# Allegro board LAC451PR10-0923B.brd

Outline 305.5 x 142.45 mm; copper layers: TOP, GND1, IN1, GND2, IN2, IN3, VCC, IN4, GND3, BOTTOM. Coordinates in mm from the lower left corner of the outline.

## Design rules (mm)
constraint set DEFAULT: min track width 0.102, pair gap 0.127
net group CLK_ITPXDP_N: nets CLK_ITPXDP_N CLK_ITPXDP_P
net group CPU_DP3_AUXN: nets CPU_DP3_AUXN CPU_DP3_AUXP
net group CRT_12_20: nets HUB_VGA_HSYNC HUB_VGA_VSYNC
net group CSS_1: nets CSSN_1 CSSP_1
net group DCIN_JACK: nets +DCIN_JACK -DCIN_JACK
net group DDR-ALERT: nets DDR_A_ALERT# DDR_B_ALERT#
net group DIFFPAIR0: nets SD/MMCDAT0/RCLK+_R SD/MMCDAT1/RCLK-_R
net group DIFFPAIR1: nets CLK_ITPXDP_N_R CLK_ITPXDP_P_R
net group GT1N: nets GT1N GT1P
net group ISUMN_GT: nets ISUMN_GT ISUMP_GT
net group ISUMN_IA: nets ISUMN_IA ISUMP_IA
net group PECI-S: nets PECI_EC PECI_EC_R
net group VSA_SEN-: nets VSA_SEN+ VSA_SEN-
net group ASYN-COMP: nets CFG_RCOMP CPU_POPIRCOMP EDP_COMP EDRAM_OPIO_RCOMP EMMC_RCOMP EOPIO_RCOMP PCH_POPIRCOMP PCIE_RCOMPN PCIE_RCOMPP SD_RCOMP SM_RCOMP0 SM_RCOMP1 SM_RCOMP2 USBCOMP
net group ASYN_12: nets H_CATERR# H_CPUPWRGD H_CPUPWRGD_R H_PROCHOT# H_PROCHOT#_R H_PROCHOT#_R1 H_THERMTRIP# H_VCCST_PWRGD H_VCCST_PWRGD_XDP PCH_PLTRST# PCH_PLTRST#_EC PLTRST_5048# PLTRST_LAN# PLTRST_TPM# PLTRST_VMM2320# THERMATRIP2# THERMATRIP3# VCCST_PWRGD XDP_OBS0 XDP_OBS0_R XDP_OBS1 XDP_OBS1_R XDP_OBS2_R XDP_OBS3_R
net group ASYN_20: nets +DDR_VREF_A_DQ +DDR_VREF_B_DQ +DDR_VREF_CA DDR_DRAMRST# DDR_DRAMRST#_R
net group BC BUS_12/15: nets BC_CLK_ECE1117 BC_CLK_ECE5048 BC_DAT_ECE1117 BC_DAT_ECE5048
net group CARD-S_12: nets SD/MMCCD# SD/MMCCLK SD/MMCCLK_R SD/MMCCMD SD/MMCCMD_R SD/MMCDAT2 SD/MMCDAT2_R SD/MMCDAT3 SD/MMCDAT3_R SDWP
net group CARD_20: nets SD/MMCDAT0/RCLK+ SD/MMCDAT1/RCLK- SD_UHS2_D0N SD_UHS2_D0P SD_UHS2_D1N SD_UHS2_D1P
net group CLINK-S_10: nets PCH_CL_CLK1 PCH_CL_DATA1 PCH_CL_RST1#
net group CLK-S_15: nets CLK_PCI_DOCK CLK_PCI_LPDEBUG CLK_PCI_MEC CLKREQ_PCIE#0 CLKREQ_PCIE#1 CLKREQ_PCIE#2 CLKREQ_PCIE#3 CLKREQ_PCIE#4 CLKREQ_PCIE#5 CPU_XDP_TCLK DAI_12MHZ# DAI_BCLK# DMIC_CLK0 DMIC_CLK_CODEC HDA_BIT_CLK HDA_BIT_CLK_R HUB_SPI_CLK I2S_BCLK I2S_MCLK JTAG_CLK MSCLK PCH_JTAG_TCK PCH_RTCRST# PCI_CLK_LPC0 PCI_CLK_LPC1 SRTCRST# SUSCLK SUSCLK_R WIGIG_32KHZ XCLK_BIASREF
net group CLK-S_20: nets CLK_27M_IN CLK_27M_OUT CLK_27M_OUT_R MEC_XTAL1 MEC_XTAL2 MEC_XTAL2_R PCH_RTCX1 PCH_RTCX2 PCH_RTCX2_R XTAL24_IN XTAL24_OUT XTAL24_OUT_R XTALI XTALO XTALO_R
net group CODEC-HP_10: nets AUD_HP_OUT_L AUD_HP_OUT_L1 AUD_HP_OUT_R AUD_HP_OUT_R1 AUD_OUT_L AUD_OUT_R
net group CODEC-SENSE_10: nets AUD_HP_NB_SENSE AUD_SENSE_A AUD_SENSE_B
net group CODEC_10: nets RING2 RING2_R SLEEVE SLEEVE_R
net group CRITICAL S_15: nets INTRUDER# PCH_DPWROK PCH_PCIE_WAKE# PCH_PWROK PCH_RSMRST# PCH_RSMRST#_Q PCIE_WAKE# PCIE_WAKE#_R RESET_OUT# RESET_OUT#_R SIO_PWRBTN# SIO_RCIN#
net group CRT_20_30: nets HUB_VGA_BLUE HUB_VGA_GREEN HUB_VGA_RED
net group DDRA-CKE: nets DDR_A_CKE0 DDR_A_CKE1 DDR_A_CKE2 DDR_A_CKE3
net group DDRA-CLK: nets DDR_A_CLK0 DDR_A_CLK1 DDR_A_CLK#0 DDR_A_CLK#1
net group DDRA-CMD: nets DDR_A_ACT# DDR_A_BA0 DDR_A_BA1 DDR_A_BG0 DDR_A_BG1 DDR_A_MA0 DDR_A_MA1 DDR_A_MA2 DDR_A_MA3 DDR_A_MA4 DDR_A_MA5 DDR_A_MA6 DDR_A_MA7 DDR_A_MA8 DDR_A_MA9 DDR_A_MA10 DDR_A_MA11 DDR_A_MA12 DDR_A_MA13 DDR_A_MA14 DDR_A_MA15 DDR_A_MA16 DDR_A_PARITY
net group DDRA-CTL: nets DDR_A_CS#0 DDR_A_CS#1 DDR_A_ODT0 DDR_A_ODT1
net group DDRA-D0: nets DDR_A_D0 DDR_A_D1 DDR_A_D2 DDR_A_D3 DDR_A_D4 DDR_A_D5 DDR_A_D6 DDR_A_D7
net group DDRA-D1: nets DDR_A_D8 DDR_A_D9 DDR_A_D10 DDR_A_D11 DDR_A_D12 DDR_A_D13 DDR_A_D14 DDR_A_D15
net group DDRA-D2: nets DDR_A_D16 DDR_A_D17 DDR_A_D18 DDR_A_D19 DDR_A_D20 DDR_A_D21 DDR_A_D22 DDR_A_D23
net group DDRA-D3: nets DDR_A_D24 DDR_A_D25 DDR_A_D26 DDR_A_D27 DDR_A_D28 DDR_A_D29 DDR_A_D30 DDR_A_D31
net group DDRA-D4: nets DDR_A_D32 DDR_A_D33 DDR_A_D34 DDR_A_D35 DDR_A_D36 DDR_A_D37 DDR_A_D38 DDR_A_D39
net group DDRA-D5: nets DDR_A_D40 DDR_A_D41 DDR_A_D42 DDR_A_D43 DDR_A_D44 DDR_A_D45 DDR_A_D46 DDR_A_D47
net group DDRA-D6: nets DDR_A_D48 DDR_A_D49 DDR_A_D50 DDR_A_D51 DDR_A_D52 DDR_A_D53 DDR_A_D54 DDR_A_D55
net group DDRA-D7: nets DDR_A_D56 DDR_A_D57 DDR_A_D58 DDR_A_D59 DDR_A_D60 DDR_A_D61 DDR_A_D62 DDR_A_D63
net group DDRA-DQS: nets DDR_A_DQS0 DDR_A_DQS1 DDR_A_DQS2 DDR_A_DQS3 DDR_A_DQS4 DDR_A_DQS5 DDR_A_DQS6 DDR_A_DQS7 DDR_A_DQS#0 DDR_A_DQS#1 DDR_A_DQS#2 DDR_A_DQS#3 DDR_A_DQS#4 DDR_A_DQS#5 DDR_A_DQS#6 DDR_A_DQS#7
net group DDRB-CKE: nets DDR_B_CKE0 DDR_B_CKE1 DDR_B_CKE2 DDR_B_CKE3
net group DDRB-CLK: nets DDR_B_CLK0 DDR_B_CLK1 DDR_B_CLK#0 DDR_B_CLK#1
net group DDRB-CMD: nets DDR_B_ACT# DDR_B_BA0 DDR_B_BA1 DDR_B_BG0 DDR_B_BG1 DDR_B_MA0 DDR_B_MA1 DDR_B_MA2 DDR_B_MA3 DDR_B_MA4 DDR_B_MA5 DDR_B_MA6 DDR_B_MA7 DDR_B_MA8 DDR_B_MA9 DDR_B_MA10 DDR_B_MA11 DDR_B_MA12 DDR_B_MA13 DDR_B_MA14 DDR_B_MA15 DDR_B_MA16 DDR_B_PARITY
net group DDRB-CTL: nets DDR_B_CS#0 DDR_B_CS#1 DDR_B_ODT0 DDR_B_ODT1
net group DDRB-D0: nets DDR_B_D0 DDR_B_D1 DDR_B_D2 DDR_B_D3 DDR_B_D4 DDR_B_D5 DDR_B_D6 DDR_B_D7
net group DDRB-D1: nets DDR_B_D8 DDR_B_D9 DDR_B_D10 DDR_B_D11 DDR_B_D12 DDR_B_D13 DDR_B_D14 DDR_B_D15
net group DDRB-D2: nets DDR_B_D16 DDR_B_D17 DDR_B_D18 DDR_B_D19 DDR_B_D20 DDR_B_D21 DDR_B_D22 DDR_B_D23
net group DDRB-D3: nets DDR_B_D24 DDR_B_D25 DDR_B_D26 DDR_B_D27 DDR_B_D28 DDR_B_D29 DDR_B_D30 DDR_B_D31
net group DDRB-D4: nets DDR_B_D32 DDR_B_D33 DDR_B_D34 DDR_B_D35 DDR_B_D36 DDR_B_D37 DDR_B_D38 DDR_B_D39
net group DDRB-D5: nets DDR_B_D40 DDR_B_D41 DDR_B_D42 DDR_B_D43 DDR_B_D44 DDR_B_D45 DDR_B_D46 DDR_B_D47
net group DDRB-D6: nets DDR_B_D48 DDR_B_D49 DDR_B_D50 DDR_B_D51 DDR_B_D52 DDR_B_D53 DDR_B_D54 DDR_B_D55
net group DDRB-D7: nets DDR_B_D56 DDR_B_D57 DDR_B_D58 DDR_B_D59 DDR_B_D60 DDR_B_D61 DDR_B_D62 DDR_B_D63
net group DDRB-DQS: nets DDR_B_DQS0 DDR_B_DQS1 DDR_B_DQS2 DDR_B_DQS3 DDR_B_DQS4 DDR_B_DQS5 DDR_B_DQS6 DDR_B_DQS7 DDR_B_DQS#0 DDR_B_DQS#1 DDR_B_DQS#2 DDR_B_DQS#3 DDR_B_DQS#4 DDR_B_DQS#5 DDR_B_DQS#6 DDR_B_DQS#7
net group DP-DDI2_12_15: nets CPU_DP2_AUXN CPU_DP2_AUXN_C CPU_DP2_AUXP CPU_DP2_AUXP_C CPU_DP2_N0 CPU_DP2_N0_C CPU_DP2_N1 CPU_DP2_N1_C CPU_DP2_N2 CPU_DP2_N2_C CPU_DP2_N3 CPU_DP2_N3_C CPU_DP2_P0 CPU_DP2_P0_C CPU_DP2_P1 CPU_DP2_P1_C CPU_DP2_P2 CPU_DP2_P2_C CPU_DP2_P3 CPU_DP2_P3_C
net group DP-HUB_12_15: nets HUB_DP0_AUXN HUB_DP0_AUXN_C HUB_DP0_AUXP HUB_DP0_AUXP_C HUB_DP0_N0 HUB_DP0_N0_C HUB_DP0_N0_R HUB_DP0_N1 HUB_DP0_N1_C HUB_DP0_N1_R HUB_DP0_N2 HUB_DP0_N2_C HUB_DP0_N2_R HUB_DP0_N3 HUB_DP0_N3_C HUB_DP0_N3_R HUB_DP0_P0 HUB_DP0_P0_C HUB_DP0_P0_R HUB_DP0_P1 HUB_DP0_P1_C HUB_DP0_P1_R HUB_DP0_P2 HUB_DP0_P2_C HUB_DP0_P2_R HUB_DP0_P3 HUB_DP0_P3_C HUB_DP0_P3_R HUB_DP1_AUXN HUB_DP1_AUXN_C HUB_DP1_AUXP HUB_DP1_AUXP_C HUB_DP1_N0 HUB_DP1_N0_C HUB_DP1_N0_R HUB_DP1_N1 HUB_DP1_N1_C HUB_DP1_N1_R HUB_DP1_N2 HUB_DP1_N2_C HUB_DP1_N2_R HUB_DP1_N3 HUB_DP1_N3_C HUB_DP1_N3_R HUB_DP1_P0 HUB_DP1_P0_C HUB_DP1_P0_R HUB_DP1_P1 HUB_DP1_P1_C HUB_DP1_P1_R HUB_DP1_P2 HUB_DP1_P2_C HUB_DP1_P2_R HUB_DP1_P3 HUB_DP1_P3_C HUB_DP1_P3_R HUB_SW1_AUXN HUB_SW1_AUXP HUB_SW2_AUXN HUB_SW2_AUXP
net group DP-SW1_12_15: nets SW1_DP1_AUXN SW1_DP1_AUXP SW1_DP1_N0 SW1_DP1_N0_C SW1_DP1_N1 SW1_DP1_N1_C SW1_DP1_N2 SW1_DP1_N2_C SW1_DP1_N3 SW1_DP1_N3_C SW1_DP1_P0 SW1_DP1_P0_C SW1_DP1_P1 SW1_DP1_P1_C SW1_DP1_P2 SW1_DP1_P2_C SW1_DP1_P3 SW1_DP1_P3_C SW1_DP2_AUXN SW1_DP2_AUXP SW1_DP2_N0 SW1_DP2_N0_C SW1_DP2_N1 SW1_DP2_N1_C SW1_DP2_N2 SW1_DP2_N2_C SW1_DP2_N3 SW1_DP2_N3_C SW1_DP2_P0 SW1_DP2_P0_C SW1_DP2_P1 SW1_DP2_P1_C SW1_DP2_P2 SW1_DP2_P2_C SW1_DP2_P3 SW1_DP2_P3_C
net group DP-SW2_12_15: nets SW2_DP1_AUXN SW2_DP1_AUXN_C SW2_DP1_AUXP SW2_DP1_AUXP_C SW2_DP1_N0 SW2_DP1_N0_C SW2_DP1_N1 SW2_DP1_N1_C SW2_DP1_N2 SW2_DP1_N2_C SW2_DP1_N3 SW2_DP1_N3_C SW2_DP1_P0 SW2_DP1_P0_C SW2_DP1_P1 SW2_DP1_P1_C SW2_DP1_P2 SW2_DP1_P2_C SW2_DP1_P3 SW2_DP1_P3_C SW2_DP2_AUXN SW2_DP2_AUXN_C SW2_DP2_AUXP SW2_DP2_AUXP_C SW2_DP2_N0 SW2_DP2_N0_C SW2_DP2_N1 SW2_DP2_N1_C SW2_DP2_N2 SW2_DP2_N2_C SW2_DP2_N3 SW2_DP2_N3_C SW2_DP2_P0 SW2_DP2_P0_C SW2_DP2_P1 SW2_DP2_P1_C SW2_DP2_P2 SW2_DP2_P2_C SW2_DP2_P3 SW2_DP2_P3_C
net group EDP_12_15: nets EDP_AUXN EDP_AUXN_C EDP_AUXP EDP_AUXP_C EDP_TXN0 EDP_TXN0_C EDP_TXN1 EDP_TXN1_C EDP_TXP0 EDP_TXP0_C EDP_TXP1 EDP_TXP1_C
net group EMI: nets BIA_PWM BIA_PWM_EC BST_3V BST_5V CLKRUN# DAI_LRCK# DMIC0 EC5048_TX EDP_BIA_PWM HOST_DEBUG_TX SD_GPIO TP_LAN_JTAG_TCK
net group ESD-GND: nets CPU_XDP_PRDY# CPU_XDP_PREQ# CPU_XDP_TDI CPU_XDP_TDO CPU_XDP_TMS CPU_XDP_TRST# PCH_JTAG_TDI PCH_JTAG_TDO PCH_JTAG_TMS POWER_SW#_MB POWER_SW_IN# RUNPWROK
net group ESD-NOCROSS-MOAT: nets CFG0 CFG1 CFG2 CFG3 CFG4 CFG5 CFG6 CFG7 CFG8 CFG9 CFG10 CFG11 CFG12 CFG13 CFG14 CFG15 CFG16 CFG17 CFG18 CFG19 SIO_EXT_SMI#
net group HDA_5_15: nets HDA_RST# HDA_RST#_R HDA_SDIN0 HDA_SDIN0_R HDA_SDOUT HDA_SDOUT_R HDA_SYNC HDA_SYNC_R
net group HDMI_12_15: nets CPU_DP1_AUXN CPU_DP1_AUXP CPU_DP1_N0 CPU_DP1_N1 CPU_DP1_N2 CPU_DP1_N3 CPU_DP1_P0 CPU_DP1_P1 CPU_DP1_P2 CPU_DP1_P3 HDMI_CLKN HDMI_CLKP HDMI_L_CLKN HDMI_L_CLKP HDMI_L_TX_N0 HDMI_L_TX_N1 HDMI_L_TX_N2 HDMI_L_TX_P0 HDMI_L_TX_P1 HDMI_L_TX_P2 HDMI_TX_N0 HDMI_TX_N1 HDMI_TX_N2 HDMI_TX_P0 HDMI_TX_P1 HDMI_TX_P2
net group I2C_15: nets I2C_HUB_SCL I2C_HUB_SDA ISH_I2C2_SCL ISH_I2C2_SCL_R ISH_I2C2_SDA ISH_I2C2_SDA_R
net group MDI_20: nets LAN_MDIN0 LAN_MDIN0_L LAN_MDIN1 LAN_MDIN1_L LAN_MDIN2 LAN_MDIN2_L LAN_MDIN3 LAN_MDIN3_L LAN_MDIP0 LAN_MDIP0_L LAN_MDIP1 LAN_MDIP1_L LAN_MDIP2 LAN_MDIP2_L LAN_MDIP3 LAN_MDIP3_L SW_LAN0_MDIN0 SW_LAN0_MDIN1 SW_LAN0_MDIN2 SW_LAN0_MDIN3 SW_LAN0_MDIP0 SW_LAN0_MDIP1 SW_LAN0_MDIP2 SW_LAN0_MDIP3 SW_LAN1_MDIN0 SW_LAN1_MDIN1 SW_LAN1_MDIN2 SW_LAN1_MDIN3 SW_LAN1_MDIP0 SW_LAN1_MDIP1 SW_LAN1_MDIP2 SW_LAN1_MDIP3
net group PCIE_12: nets PCIE_PRX_C_DTX_N9 PCIE_PRX_C_DTX_N10 PCIE_PRX_C_DTX_N11 PCIE_PRX_C_DTX_N12 PCIE_PRX_C_DTX_P9 PCIE_PRX_C_DTX_P10 PCIE_PRX_C_DTX_P11 PCIE_PRX_C_DTX_P12 PCIE_PRX_C_RD_DTX_N11 PCIE_PRX_C_RD_DTX_N12 PCIE_PRX_C_RD_DTX_P11 PCIE_PRX_C_RD_DTX_P12 PCIE_PRX_DTX_N3 PCIE_PRX_DTX_N5 PCIE_PRX_DTX_N6 PCIE_PRX_DTX_N9 PCIE_PRX_DTX_N10 PCIE_PRX_DTX_N11 PCIE_PRX_DTX_N12 PCIE_PRX_DTX_P3 PCIE_PRX_DTX_P5 PCIE_PRX_DTX_P6 PCIE_PRX_DTX_P9 PCIE_PRX_DTX_P10 PCIE_PRX_DTX_P11 PCIE_PRX_DTX_P12 PCIE_PRX_RD_DTX_N11 PCIE_PRX_RD_DTX_N12 PCIE_PRX_RD_DTX_P11 PCIE_PRX_RD_DTX_P12 PCIE_PTX_C_DRX_N3 PCIE_PTX_C_DRX_N5 PCIE_PTX_C_DRX_N6 PCIE_PTX_C_DRX_N9 PCIE_PTX_C_DRX_N10 PCIE_PTX_C_DRX_N11 PCIE_PTX_C_DRX_N12 PCIE_PTX_C_DRX_P3 PCIE_PTX_C_DRX_P5 PCIE_PTX_C_DRX_P6 PCIE_PTX_C_DRX_P9 PCIE_PTX_C_DRX_P10 PCIE_PTX_C_DRX_P11 PCIE_PTX_C_DRX_P12 PCIE_PTX_C_RD_DRX_N11 PCIE_PTX_C_RD_DRX_N12 PCIE_PTX_C_RD_DRX_P11 PCIE_PTX_C_RD_DRX_P12 PCIE_PTX_DRX_N3 PCIE_PTX_DRX_N5 PCIE_PTX_DRX_N6 PCIE_PTX_DRX_N9 PCIE_PTX_DRX_N10 PCIE_PTX_DRX_N11 PCIE_PTX_DRX_N12 PCIE_PTX_DRX_P3 PCIE_PTX_DRX_P5 PCIE_PTX_DRX_P6 PCIE_PTX_DRX_P9 PCIE_PTX_DRX_P10 PCIE_PTX_DRX_P11 PCIE_PTX_DRX_P12 PCIE_PTX_RD_DRX_N11 PCIE_PTX_RD_DRX_N12 PCIE_PTX_RD_DRX_P11 PCIE_PTX_RD_DRX_P12
net group PLAT-CLK_12: nets CLK_PCIE_N0 CLK_PCIE_N1 CLK_PCIE_N2 CLK_PCIE_N3 CLK_PCIE_N4 CLK_PCIE_N5 CLK_PCIE_P0 CLK_PCIE_P1 CLK_PCIE_P2 CLK_PCIE_P3 CLK_PCIE_P4 CLK_PCIE_P5
net group RJ45_20: nets RJ45_MDIN0 RJ45_MDIN1 RJ45_MDIN2 RJ45_MDIN3 RJ45_MDIP0 RJ45_MDIP1 RJ45_MDIP2 RJ45_MDIP3
net group SATA_12: nets SATA_PRX_C_DTX_N1 SATA_PRX_C_DTX_P1 SATA_PRX_DTX_N1 SATA_PRX_DTX_P1 SATA_PTX_C_DRX_N1 SATA_PTX_C_DRX_P1 SATA_PTX_DRX_N1 SATA_PTX_DRX_P1
net group SD-NOCROSS-MOAT: nets DOCK_POR_RST# JTAG_RST# ME_SUS_PWR_ACK SUSACK# USB_OC0# USB_OC1# USB_OC2#
net group SENSE_25: nets VCC_GT_SENSE VCCIO_SENSE VCCSENSE VSS_GT_SENSE VSSIO_SENSE VSSSENSE
net group SIM_15: nets UIM_CLK UIM_DATA UIM_RESET
net group SMB_15: nets CHARGER_SMBCLK CHARGER_SMBDAT CLK_KBD CLK_MSE CLK_TP_SIO CPU_DP1_CTRL_CLK CPU_DP1_CTRL_DATA CPU_DP2_CTRL_CLK CPU_DP2_CTRL_DATA DAT_KBD DAT_MSE DAT_TP_SIO DDR_XDP_WAN_SMBCLK DDR_XDP_WAN_SMBDAT DOCK_SMB_CLK DOCK_SMB_DAT GPU_SMBCLK GPU_SMBDAT HDMI_CTRL_CLK HDMI_CTRL_DATA HUB_DP0_SCL HUB_DP0_SDA HUB_DP1_SCL HUB_DP1_SDA HUB_VGA_SCL HUB_VGA_SDA MEM_SMBCLK MEM_SMBDATA PBAT_SMBCLK PBAT_SMBCLK_C PBAT_SMBDAT PBAT_SMBDAT_C SML0_SMBCLK SML0_SMBDATA SML1_SMBCLK SML1_SMBDATA USH_SMBCLK USH_SMBDAT
net group SPI-CLK_15: nets PCH_SPI_CLK PCH_SPI_CLK_0_R PCH_SPI_CLK_1_R PCH_SPI_CLK_2_R PCH_SPI_CLK_R1
net group SPI-S_5: nets HUB_SPI_CS# HUB_SPI_DIN HUB_SPI_DO HUB_SPI_HOLD HUB_SPI_WP# PCH_SPI_CS#0 PCH_SPI_CS#0_R1 PCH_SPI_CS#0_R2 PCH_SPI_CS#1 PCH_SPI_CS#1_R1 PCH_SPI_CS#1_R2 PCH_SPI_CS#2 PCH_SPI_CS#2_R PCH_SPI_D0 PCH_SPI_D0_0_R PCH_SPI_D0_1_R PCH_SPI_D0_2_R PCH_SPI_D0_R1 PCH_SPI_D1 PCH_SPI_D1_0_R PCH_SPI_D1_1_R PCH_SPI_D1_2_R PCH_SPI_D1_R1 PCH_SPI_D2 PCH_SPI_D2_0_R PCH_SPI_D2_1_R PCH_SPI_D2_R1 PCH_SPI_D3 PCH_SPI_D3_0_R PCH_SPI_D3_1_R PCH_SPI_D3_R1 PCH_SPI_DO2_XDP PCH_SPI_DO_XDP
net group SPK_20: nets INT_SPK_L+ INT_SPK_L- INT_SPK_R+ INT_SPK_R- INT_SPKR_L+ INT_SPKR_L- INT_SPKR_R+ INT_SPKR_R-
net group SVID_18: nets H_CPU_SVIDALRT# VIDALERT_N VIDSCLK VIDSOUT
net group THERMAL_20: nets DOCK_DCIN_IS+ DOCK_DCIN_IS- REM_DIODE1_N REM_DIODE1_P REM_DIODE2_N REM_DIODE2_P REM_DIODE4_N REM_DIODE4_P
net group USB20_12: nets SW_USB20_N1 SW_USB20_P1 USB20_N1 USB20_N1_R USB20_N2 USB20_N2_R USB20_N3 USB20_N3_R USB20_N4 USB20_N4_R USB20_N5 USB20_N6 USB20_N7 USB20_N8 USB20_N9 USB20_N9_R USB20_N10 USB20_P1 USB20_P1_R USB20_P2 USB20_P2_R USB20_P3 USB20_P3_R USB20_P4 USB20_P4_R USB20_P5 USB20_P6 USB20_P7 USB20_P8 USB20_P9 USB20_P9_R USB20_P10
net group USB30_12: nets USB3_PRX_DTX_N1 USB3_PRX_DTX_N2 USB3_PRX_DTX_N3 USB3_PRX_DTX_N4 USB3_PRX_DTX_N5 USB3_PRX_DTX_P1 USB3_PRX_DTX_P2 USB3_PRX_DTX_P3 USB3_PRX_DTX_P4 USB3_PRX_DTX_P5 USB3_PRX_L_DTX_N1 USB3_PRX_L_DTX_N3 USB3_PRX_L_DTX_N4 USB3_PRX_L_DTX_N5 USB3_PRX_L_DTX_P1 USB3_PRX_L_DTX_P3 USB3_PRX_L_DTX_P4 USB3_PRX_L_DTX_P5 USB3_PTX_C_DRX_N1 USB3_PTX_C_DRX_N3 USB3_PTX_C_DRX_N4 USB3_PTX_C_DRX_N5 USB3_PTX_C_DRX_P1 USB3_PTX_C_DRX_P3 USB3_PTX_C_DRX_P4 USB3_PTX_C_DRX_P5 USB3_PTX_DRX_N1 USB3_PTX_DRX_N2 USB3_PTX_DRX_N3 USB3_PTX_DRX_N4 USB3_PTX_DRX_N5 USB3_PTX_DRX_P1 USB3_PTX_DRX_P2 USB3_PTX_DRX_P3 USB3_PTX_DRX_P4 USB3_PTX_DRX_P5 USB3_PTX_L_DRX_N1 USB3_PTX_L_DRX_N3 USB3_PTX_L_DRX_N4 USB3_PTX_L_DRX_N5 USB3_PTX_L_DRX_P1 USB3_PTX_L_DRX_P3 USB3_PTX_L_DRX_P4 USB3_PTX_L_DRX_P5
net group W10: nets BAT1_LED# BAT2_LED# BATT_WHITE# BATT_YELLOW#
nets with their own width: min track width 0.254; nets +1.0VO_DSW +3.3V_SPI +3.3V_SPI_R +5V_ALWP N25124064 PWM1_GT PWM_IA PWM_VSA
nets with their own width: min track width 0.508; nets +0.9V_LAN +1.0V_AMPHYPLL +1.0V_APLL +1.0V_APLLEBB +1.0V_CLK1 +1.0V_CLK2 +1.0V_CLK3 +1.0V_CLK4 +1.0V_CLK5 +1.0V_CLK6 +1.0V_DTS +1.0V_MPHYAON +1.0V_PRIM +1.0V_PRIM_CORE +1.0V_PRIM_XDP +1.0V_VCCST +1.0V_VCCST_C +1.0V_VCCSTG +1.2V_LDO +1.5V_RUN +1.5V_RUN_AUDIO +1.8V_RUN_CARD +3.3V_ALW +3.3V_ALW2 +3.3V_ALW_DSW +3.3V_ALW_UE1 +3.3V_ALW_UE2 +3.3V_ALWP +3.3V_CAM +3.3V_M +3.3V_M_TPM +3.3V_M_UZ8 +3.3V_MMI_AUX +3.3V_RTC_LDO +3.3V_RUN +3.3V_RUN_AUDIO +3.3V_RUN_UZ3 +3.3V_TP +5V_ALW +5V_ALW2 +CAP_LDO +COINCELL +DC_IN +DC_IN_SS +DCIN +DDR_VREF_A_CA +DOCK_PWR_BAR +GND_CHASSIS +LOM_VCT +MIC1_VREF_OUT +NBDOCK_DC_IN_SS +PBATT +PECI_VREF +PWR_SRC +PWR_SRC_AC +RSVD_VCC3P3_1 +RTC_CELL +RTC_CELL_VBAT +SDC_IN +UZ12_TPM +VCC_CORE +VCC_CORE_G0 +VCC_CORE_G1 +VCC_GT +VCC_SA +VCC_SFR_OC +VCHGR +VDDA_AVDD1 +VDDA_PVDD +VR_CAP +VREFOUT +Z4012 ADJ GND GNDA N15438178 N36519054
nets with their own width: min track width 0.762; nets +1.0V_SRAM +3.3V_LAN_OUT
nets with their own width: min track width 1.016; nets +1.0V_RUN_VMM +1.0V_VMM_VDD +1.0V_VMM_VDDTX +1.0VS_VCCIO +1.8V_PGPPF +1.8V_PRIM +3.3V_1.8V_PGPPG +3.3V_ALW_PCH +3.3V_LAN +3.3V_LAN_UZ2 +3.3V_PGPPB +3.3V_PGPPC +3.3V_PGPPD +3.3V_PGPPE +3.3V_RUN_CARD +3.3V_RUN_VDDA +3.3V_RUN_VDDIO +3.3V_RUN_VMM +5V_RUN_AUDIO +5V_RUN_PVDD +V_DDR_REF
nets with their own width: min track width 1.27; nets +3.3V_MMI_IN
nets with their own width: min track width 1.524; nets +3.3V_1.8V_PGPPA +EDP_VDD +LCDVDD
nets with their own width: min track width 2.032; nets +1.0V_MPHYGT +3.3V_HDD +3.3V_WLAN +3.3V_WLAN_UZ3 +5V_RUN +BL_PWR_SRC +USB_LEFT_PWR +USB_REAR_PWR +VDISPLAY_VCC +VHDMI_VCC
nets with their own width: min track width 2.54; nets +3.3V_WWAN +5V_USB_CHG_PWR

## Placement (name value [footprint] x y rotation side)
C33  4.7U_0805_25V6-K  [C_0805]  174.09 126.6 270 bottom
C42  4.7P_0402_50V8C  [C_0402]  153.13 126.2 90 bottom
C43  4.7P_0402_50V8C  [C_0402]  155.84 126.2 90 bottom
C263  1U_0402_6.3V6K  [C_0402]  284.53 121.95 180 bottom
C294  0.1U_0402_25V6  [C_0402]  136.75 133.43 90 top
C295  0.1U_0402_25V6  [C_0402]  137.89 125.33 270 bottom
C296  0.1U_0402_25V6  [C_0402]  137.64 133.43 90 top
C297  0.1U_0402_25V6  [C_0402]  138.78 125.33 270 bottom
C298  0.1U_0402_25V6  [C_0402]  138.53 133.43 90 top
C299  0.1U_0402_25V6  [C_0402]  139.67 125.33 270 bottom
C300  0.1U_0402_25V6  [C_0402]  142.34 125.33 270 bottom
C301  0.1U_0402_25V6  [C_0402]  143.23 125.33 270 bottom
C302  0.1U_0402_25V6  [C_0402]  137.01 125.33 270 bottom
C303  0.1U_0402_25V6  [C_0402]  139.42 133.43 90 top
C304  0.1U_0402_25V6  [C_0402]  140.56 125.33 270 bottom
C305  0.1U_0402_25V6  [C_0402]  140.31 133.43 90 top
C306  0.1U_0402_25V6  [C_0402]  141.45 125.33 270 bottom
C307  0.1U_0402_25V6  [C_0402]  141.2 133.43 90 top
C308  0.1U_0402_25V6  [C_0402]  142.09 133.43 90 top
C309  0.1U_0402_25V6  [C_0402]  142.97 133.43 90 top
C310  0.033U_0402_16V7K  [C_0402]  145.01 127.11 270 bottom
C311  0.033U_0402_16V7K  [C_0402]  143.86 136.13 270 top
C312  0.01UF_0402_25V7K  [C_0402]  148.44 135.47 90 top
C313  0.01UF_0402_25V7K  [C_0402]  149.32 135.47 90 top
C314  0.01UF_0402_25V7K  [C_0402]  150.21 136.38 270 top
C315  0.01UF_0402_25V7K  [C_0402]  151.1 136.38 270 top
C316  1U_0402_6.3V6K  [C_0402]  176.43 124.82 180 bottom
C317  0.1U_0603_50V7K  [C_0603]  172.57 126.7 270 bottom
C318  0.1U_0603_50V7K  [C_0603]  135.04 132.37 0 top
C319  4.7P_0402_50V8C  [C_0402]  165.2 126.2 90 bottom
CA1  680P_0402_50V7K  [C_0402]  284.4 48.17 180 top
CA2  220P_0402_50V7K  [C_0402]  284.4 46.14 180 top
CA3  220P_0402_50V7K  [C_0402]  284.4 54.26 180 top
CA4  680P_0402_50V7K  [C_0402]  284.4 51.09 180 top
CA5  100P_0402_50V8J  [C_0402]  99.53 114.83 145 top
CA6  100P_0402_50V8J  [C_0402]  100.04 115.6 145 top
CA7  0.1U_0201_10V6K  [C_0201]  98.78 114.25 145 top
CA8  0.1U_0201_10V6K  [C_0201]  295.63 66.72 270 top
CA9  10U_0603_10V6M  [C_0603]  294.55 68.3 270 top
CA10  4.7U_0603_6.3V6K  [C_0603]  284.01 67.15 270 top
CA11  0.1U_0201_10V6K  [C_0201]  284.4 72.93 180 top
CA12  680P_0402_50V7K  [C_0402]  288.47 48.04 180 top
CA13  680P_0402_50V7K  [C_0402]  287.11 49.5 0 top
CA16  4.7U_0603_6.3V6K  [C_0603]  290.99 77.12 0 top
CA17  0.1U_0201_10V6K  [C_0201]  293.33 74.67 270 top
CA18  4.7U_0603_6.3V6K  [C_0603]  293.41 75.69 0 top
CA19  1000P_0402_50V7K  [C_0402]  280.13 32.24 270 top
CA22  1000P_0402_50V7K  [C_0402]  280.13 39.86 270 top
CA23  1000P_0402_50V7K  [C_0402]  280.13 33.1 90 top
CA24  1000P_0402_50V7K  [C_0402]  280.13 25.61 90 top
CA25  10U_0603_10V6M  [C_0603]  296.39 70.84 0 top
CA26  1U_0603_10V6K  [C_0603]  292.68 65.18 270 top
CA27  0.1U_0402_25V6  [C_0402]  285.18 63.95 90 top
CA28  0.1U_0402_25V6  [C_0402]  284.29 63.95 90 top
CA29  1U_0603_10V6K  [C_0603]  294.61 73 90 top
CA31  1U_0603_10V6K  [C_0603]  284.39 76.11 180 top
CA33  10P_0402_50V8J  [C_0402]  282.66 71.22 0 top
CA35  2.2U_0402_6.3V6M  [C_0402]  294.62 65.95 180 top
CA41  0.1U_0402_25V6  [C_0402]  281.45 61.12 0 top
CA43  4.7U_0603_6.3V6K  [C_0603]  290.01 64.41 270 top
CA44  4.7U_0603_6.3V6K  [C_0603]  291.21 64.41 270 top
CA45  0.1U_0201_10V6K  [C_0201]  286.7 76.74 180 top
CA46  10U_0603_10V6M  [C_0603]  287.94 77.89 0 top
CA47  0.1U_0201_10V6K  [C_0201]  288.06 76.74 0 top
CA48  10U_0603_10V6M  [C_0603]  286.93 77.89 180 top
CA49  1U_0603_10V6K  [C_0603]  297.78 72.04 180 top
CA50  0.1U_0201_10V6K  [C_0201]  284.14 68.1 180 top
CA51  4.7U_0603_6.3V6K  [C_0603]  294.42 60.87 0 top
CA52  4.7U_0603_6.3V6K  [C_0603]  291.05 75.92 0 top
CA53  4.7U_0603_6.3V6K  [C_0603]  281.53 70.07 90 top
CA54  22P_0402_50V8J  [C_0402]  281.79 73.94 90 top
CC3  27P_0402_50V8J  [C_0402]  177.7 70.17 90 top
CC4  27P_0402_50V8J  [C_0402]  176.81 70.17 90 top
CC5  27P_0402_50V8J  [C_0402]  180.05 70.11 90 top
CC6  27P_0402_50V8J  [C_0402]  179.16 70.11 90 top
CC7  33P_0402_50V8J  [C_0402]  187.11 89.55 180 bottom
CC8  33P_0402_50V8J  [C_0402]  185.39 100.03 90 bottom
CC9  0.1U_0201_10V6K  [C_0201]  187.17 100.03 90 bottom
CC10  0.1U_0201_10V6K  [C_0201]  186.88 93.86 270 bottom
CC21  15P_0402_50V8J  [C_0402]  153.59 111.11 180 bottom
CC22  15P_0402_50V8J  [C_0402]  154.45 111.11 0 bottom
CC23  15P_0402_50V8J  [C_0402]  179.49 89.45 270 top
CC24  1U_0402_6.3V6K  [C_0402]  168.64 73.34 270 top
CC25  1U_0402_6.3V6K  [C_0402]  203.81 78.19 90 bottom
CC26  12P_0402_50V8J  [C_0402]  181.32 89.44 0 top
CC27  22P_0402_50V8J  [C_0402]  165.38 69.59 90 top
CC28  0.1U_0201_10V6K  [C_0201]  129.59 125.08 0 top
CC29  0.1U_0201_10V6K  [C_0201]  129.55 124.01 0 top
CC30  0.1U_0201_10V6K  [C_0201]  145.59 117.7 180 bottom
CC32  0.1U_0402_25V6  [C_0402]  135.27 118.56 90 top
CC33  0.1U_0402_25V6  [C_0402]  127.61 128.77 270 top
CC174  10U_0402_6.3V6M  [C_0402]  144.74 72.59 180 top
CC175  10U_0402_6.3V6M  [C_0402]  150.92 74.98 0 top
CC176  10U_0402_6.3V6M  [C_0402]  159.05 74.43 270 top
CC177  10U_0402_6.3V6M  [C_0402]  146.55 74.52 270 top
CC178  10U_0402_6.3V6M  [C_0402]  151.89 71.95 270 top
CC179  10U_0402_6.3V6M  [C_0402]  155.5 72.11 270 top
CC181  1U_0402_6.3V6K  [C_0402]  148.55 88.36 180 top
CC182  1U_0402_6.3V6K  [C_0402]  155.65 86.55 90 top
CC185  1U_0402_6.3V6K  [C_0402]  149.37 89.25 0 top
CC186  1U_0402_6.3V6K  [C_0402]  149.37 88.36 0 top
CC194  1U_0402_6.3V6K  [C_0402]  152.89 87.56 180 top
CC195  1U_0402_6.3V6K  [C_0402]  164.41 106.08 90 bottom
CC199  1U_0402_6.3V6K  [C_0402]  159.22 112.73 0 top
CC202  1U_0402_6.3V6K  [C_0402]  161.19 98.67 180 top
CC203  1U_0402_6.3V6K  [C_0402]  164.96 98.2 270 top
CC204  1U_0402_6.3V6K  [C_0402]  173.87 88.16 0 top
CC205  1U_0402_6.3V6K  [C_0402]  163.01 90.39 270 top
CC206  1U_0402_6.3V6K  [C_0402]  162.39 92.46 90 top
CC207  1U_0402_6.3V6K  [C_0402]  165.25 91.58 180 top
CC208  1U_0402_6.3V6K  [C_0402]  165.05 93.3 0 top
CC209  1U_0402_6.3V6K  [C_0402]  163.27 92.47 0 top
CC210  47U_0805_6.3V6M  [C_0805]  176.86 114.14 0 top
CC211  1U_0402_6.3V6K  [C_0402]  164.98 94.95 0 top
CC212  1U_0402_6.3V6K  [C_0402]  174.83 91.21 270 top
CC213  1U_0402_6.3V6K  [C_0402]  162.1 87.28 180 top
CC214  0.1U_0201_10V6K  [C_0201]  177.76 77 90 bottom
CC215  1U_0402_6.3V6K  [C_0402]  161.6 89.49 90 top
CC216  1U_0402_6.3V6K  [C_0402]  169.85 111.29 180 top
CC217  1U_0402_6.3V6K  [C_0402]  162.13 91.42 180 top
CC218  1U_0402_6.3V6K  [C_0402]  163.04 95.01 180 top
CC219  47U_0805_6.3V6M  [C_0805]  170.03 110.44 90 bottom
CC220  47U_0805_6.3V6M  [C_0805]  163.42 111.45 90 top
CC221  47U_0805_6.3V6M  [C_0805]  168.25 110.44 90 bottom
CC222  1U_0402_6.3V6K  [C_0402]  168.22 93.25 180 top
CC223  0.1U_0201_10V6K  [C_0201]  173.02 88.01 90 top
CC224  1U_0402_6.3V6K  [C_0402]  172.26 87.57 90 top
CC225  47U_0805_6.3V6M  [C_0805]  191.1 96.18 90 top
CC226  47U_0805_6.3V6M  [C_0805]  162.6 110.44 90 bottom
CC248  10U_0402_6.3V6M  [C_0402]  148.55 87.47 180 top
CC249  10U_0402_6.3V6M  [C_0402]  149.37 87.47 0 top
CC250  1U_0402_6.3V6K  [C_0402]  157.38 88.78 90 top
CC251  1U_0402_6.3V6K  [C_0402]  148.55 89.25 180 top
CC252  1U_0402_6.3V6K  [C_0402]  157.44 87.45 180 top
CC253  1U_0402_6.3V6K  [C_0402]  156.49 88.78 90 top
CC254  1U_0402_6.3V6K  [C_0402]  147.95 74.52 270 top
CC255  1U_0402_6.3V6K  [C_0402]  150.8 74.05 270 top
CC256  1U_0402_6.3V6K  [C_0402]  156.85 73.3 270 top
CC257  1U_0402_6.3V6K  [C_0402]  153.78 74.18 270 top
CC264  1U_0402_6.3V6K  [C_0402]  171.36 110.32 90 bottom
CC265  1U_0402_6.3V6K  [C_0402]  166.01 89.9 180 top
CC266  0.01UF_0402_25V7K  [C_0402]  177.25 66.96 270 top
CC269  0.1U_0402_25V6  [C_0402]  110.16 122.34 180 bottom
CC270  0.1U_0201_10V6K  [C_0201]  169.44 71.48 180 top
CC271  47U_0805_6.3V6M  [C_0805]  178.5 64.4 270 top
CC272  47U_0805_6.3V6M  [C_0805]  276.92 3.46 180 top
CC273  47U_0805_6.3V6M  [C_0805]  166.15 119.58 90 bottom
CC274  47U_0805_6.3V6M  [C_0805]  191.09 91.77 90 top
CC279  22U_0603_6.3V6M  [C_0603]  180.82 69.07 0 top
CC280  22U_0603_6.3V6M  [C_0603]  180.82 67.86 0 top
CC281  0.1U_0201_10V6K  [C_0201]  173.52 111.74 270 bottom
CC282  22U_0603_6.3V6M  [C_0603]  146.02 88.74 270 top
CC283  22U_0603_6.3V6M  [C_0603]  165.2 117.13 180 top
CC284  22U_0603_6.3V6M  [C_0603]  165.2 115.86 180 top
CC285  22U_0603_6.3V6M  [C_0603]  165.07 118.84 180 top
CC286  22U_0603_6.3V6M  [C_0603]  160.82 72.81 270 top
CC287  22U_0603_6.3V6M  [C_0603]  141.15 118.28 90 top
CC288  1U_0402_6.3V6K  [C_0402]  160.68 89.51 90 top
CC294  22U_0603_6.3V6M  [C_0603]  139.16 74.27 270 top
CC295  22U_0603_6.3V6M  [C_0603]  149.46 71.98 270 top
CC296  22U_0603_6.3V6M  [C_0603]  158.85 72.34 270 top
CC297  10U_0402_6.3V6M  [C_0402]  151.13 87.18 90 top
CC300  100P_0402_50V8J  [C_0402]  125.12 99.6 0 bottom
CC301  100P_0402_50V8J  [C_0402]  133.41 110.47 180 bottom
CC302  0.1U_0402_25V6  [C_0402]  177.51 106.17 0 bottom
CC303  0.1U_0402_25V6  [C_0402]  141.72 107.88 90 bottom
CC304  0.1U_0402_25V6  [C_0402]  139.98 107.63 90 bottom
CC305  0.1U_0402_25V6  [C_0402]  138.36 110.42 180 bottom
CC306  0.1U_0402_25V6  [C_0402]  130.48 117.74 180 bottom
CC307  0.1U_0402_25V6  [C_0402]  110.16 124.48 180 bottom
CC308  0.1U_0402_25V6  [C_0402]  145.4 118.87 0 bottom
CC310  0.1U_0402_25V6  [C_0402]  128.19 108.86 180 bottom
CC311  15P_0402_50V8J  [C_0402]  163.54 72.75 180 top
CC312  0.1U_0402_25V6  [C_0402]  137.07 108.16 180 bottom
CC313  0.1U_0402_25V6  [C_0402]  190.55 85.58 0 top
CC314  0.1U_0402_25V6  [C_0402]  192.47 96.41 90 top
CD2  1U_0402_6.3V6K  [C_0402]  119.97 49.63 270 top
CD3  1U_0402_6.3V6K  [C_0402]  111.88 41.8 90 top
CD4  1U_0402_6.3V6K  [C_0402]  113.43 41.86 90 top
CD6  0.1U_0402_25V6  [C_0402]  107.74 44.83 90 top
CD7  1U_0402_6.3V6K  [C_0402]  118.42 41.5 90 top
CD8  1U_0402_6.3V6K  [C_0402]  110.37 41.68 90 top
CD9  1U_0402_6.3V6K  [C_0402]  118.46 49.6 270 top
CD10  1U_0402_6.3V6K  [C_0402]  115.08 49.68 270 top
CD11  1U_0402_6.3V6K  [C_0402]  111.85 49.63 270 top
CD12  10U_0603_10V6M  [C_0603]  121.83 41.32 90 top
CD13  10U_0603_10V6M  [C_0603]  109.19 41.22 90 top
CD14  10U_0603_10V6M  [C_0603]  110.32 50.15 270 top
CD15  10U_0603_10V6M  [C_0603]  116.75 50.15 270 top
CD16  10U_0603_10V6M  [C_0603]  123.49 41.31 90 top
CD17  10U_0603_10V6M  [C_0603]  115.05 41.35 90 top
CD18  10U_0603_10V6M  [C_0603]  113.43 50.14 270 top
CD19  10U_0603_10V6M  [C_0603]  121.63 50.15 270 top
CD20  330U_D3_2.5VY_R6M  [C_D3]  129.87 53.37 0 top
CD24  1U_0402_6.3V6K  [C_0402]  148.94 42.38 180 top
CD25  1U_0402_6.3V6K  [C_0402]  149.18 44.17 180 top
CD26  1U_0402_6.3V6K  [C_0402]  148.93 41.46 180 top
CD27  1U_0402_6.3V6K  [C_0402]  150.01 44.18 0 top
CD28  10U_0603_10V6M  [C_0603]  149.45 46.41 180 top
CD29  10U_0603_10V6M  [C_0603]  149.6 45.21 180 top
CD30  0.1U_0201_10V6K  [C_0201]  84.02 39.4 180 top
CD31  2.2U_0402_6.3V6M  [C_0402]  149.5 50.68 270 top
CD32  0.1U_0201_10V6K  [C_0201]  148.75 50.36 270 top
CD35  0.1U_0402_25V6  [C_0402]  190.84 41.04 180 top
CD36  0.022U_0402_16V7K  [C_0402]  129.69 41.25 90 top
CD37  1U_0402_6.3V6K  [C_0402]  192.68 41.35 90 top
CD38  1U_0402_6.3V6K  [C_0402]  195.5 41.4 90 top
CD39  1U_0402_6.3V6K  [C_0402]  198.98 41.18 90 top
CD40  1U_0402_6.3V6K  [C_0402]  205.33 49.89 270 top
CD41  1U_0402_6.3V6K  [C_0402]  201.78 49.89 270 top
CD42  1U_0402_6.3V6K  [C_0402]  194.03 50.02 270 top
CD43  1U_0402_6.3V6K  [C_0402]  191.23 50.02 270 top
CD44  1U_0402_6.3V6K  [C_0402]  205.32 41.58 90 top
CD45  10U_0603_10V6M  [C_0603]  192.57 50.08 270 top
CD46  10U_0603_10V6M  [C_0603]  189.66 50.08 270 top
CD47  10U_0603_10V6M  [C_0603]  200.25 50.52 270 top
CD48  10U_0603_10V6M  [C_0603]  203.55 50.52 270 top
CD49  10U_0603_10V6M  [C_0603]  203.46 41.26 90 top
CD50  10U_0603_10V6M  [C_0603]  200.28 41 90 top
CD51  10U_0603_10V6M  [C_0603]  197.34 41.11 90 top
CD52  10U_0603_10V6M  [C_0603]  194.02 41.17 90 top
CD53  330U_D3_2.5VY_R6M  [C_D3]  209.85 54.14 0 top
CD54  0.022U_0402_16V7K  [C_0402]  208.82 41.11 0 top
CD57  1U_0402_6.3V6K  [C_0402]  228.72 42.76 180 top
CD58  1U_0402_6.3V6K  [C_0402]  229.5 44.18 180 top
CD59  1U_0402_6.3V6K  [C_0402]  230.83 44.47 0 top
CD60  1U_0402_6.3V6K  [C_0402]  230.34 43.61 0 top
CD61  10U_0603_10V6M  [C_0603]  229.93 46.6 180 top
CD62  10U_0603_10V6M  [C_0603]  229.94 45.23 180 top
CD63  2.2U_0402_6.3V6M  [C_0402]  229.23 49.86 180 top
CD64  0.1U_0201_10V6K  [C_0201]  229.07 49.09 180 top
CD70  1U_0402_6.3V6K  [C_0402]  150.43 48.81 180 top
CD71  1U_0402_6.3V6K  [C_0402]  150.43 47.94 180 top
CD72  10U_0603_10V6M  [C_0603]  151.48 48.21 90 top
CD73  10U_0603_10V6M  [C_0603]  152.73 48.21 90 top
CD74  1U_0402_6.3V6K  [C_0402]  231.94 48.05 270 top
CD75  1U_0402_6.3V6K  [C_0402]  231.06 48.05 270 top
CD76  10U_0603_10V6M  [C_0603]  234.22 48.05 270 top
CD77  10U_0603_10V6M  [C_0603]  233 48.05 270 top
CD78  1U_0402_6.3V6K  [C_0402]  125.16 41.89 90 top
CD79  1U_0402_6.3V6K  [C_0402]  130.1 39.56 0 top
CD80  1U_0402_6.3V6K  [C_0402]  120.03 43.3 90 top
CD81  1U_0402_6.3V6K  [C_0402]  102.79 51.79 0 top
CD82  1U_0402_6.3V6K  [C_0402]  134.3 50.52 180 top
CD83  1U_0402_6.3V6K  [C_0402]  90.76 51.7 180 top
CD84  1U_0402_6.3V6K  [C_0402]  86.26 41.04 0 top
CD85  1U_0402_6.3V6K  [C_0402]  101.95 51.79 180 top
CD86  10U_0603_10V6M  [C_0603]  91.79 51.91 0 top
CD87  10U_0603_10V6M  [C_0603]  125.8 52.33 0 top
CD88  10U_0603_10V6M  [C_0603]  124.57 52.35 180 top
CD89  10U_0603_10V6M  [C_0603]  110.75 52.08 180 top
CD90  10U_0603_10V6M  [C_0603]  116.89 52.14 0 top
CD91  10U_0603_10V6M  [C_0603]  106.82 41.26 180 top
CD92  10U_0603_10V6M  [C_0603]  115.82 52.14 180 top
CD93  10U_0603_10V6M  [C_0603]  97.42 41.08 0 top
CD94  10U_0603_10V6M  [C_0603]  220.38 39.42 0 top
CD95  10U_0603_10V6M  [C_0603]  182.39 49.65 270 top
CD96  10U_0603_10V6M  [C_0603]  185.3 49.65 270 top
CD97  10U_0603_10V6M  [C_0603]  201.89 41.14 90 top
CD98  10U_0603_10V6M  [C_0603]  172.76 51.34 0 top
CD99  10U_0603_10V6M  [C_0603]  188.48 40.95 270 top
CD100  10U_0603_10V6M  [C_0603]  206.07 52.08 0 top
CD101  10U_0603_10V6M  [C_0603]  178.13 40.99 270 top
CD102  1U_0402_6.3V6K  [C_0402]  186.89 40.48 270 top
CD103  1U_0402_6.3V6K  [C_0402]  210.32 39.53 180 top
CD104  1U_0402_6.3V6K  [C_0402]  196.86 52.05 180 top
CD105  1U_0402_6.3V6K  [C_0402]  171.6 51.95 180 top
CD106  1U_0402_6.3V6K  [C_0402]  197.7 52.02 0 top
CD107  1U_0402_6.3V6K  [C_0402]  190.41 42.24 90 top
CD108  1U_0402_6.3V6K  [C_0402]  176.46 40.37 270 top
CD109  1U_0402_6.3V6K  [C_0402]  169.87 40.76 270 top
CE1  10U_0603_10V6M  [C_0603]  263.5 56.99 270 top
CE2  0.1U_0201_10V6K  [C_0201]  231.95 59.42 270 top
CE3  0.1U_0201_10V6K  [C_0201]  241.02 63.66 0 top
CE4  0.1U_0201_10V6K  [C_0201]  238.73 74.76 90 top
CE5  0.1U_0201_10V6K  [C_0201]  225.47 62.14 180 top
CE6  0.1U_0201_10V6K  [C_0201]  228.83 75.01 90 top
CE7  4.7U_0603_6.3V6K  [C_0603]  225.46 63.41 180 top
CE8  .047U_0402_16V7K  [C_0402]  228.39 59.42 270 top
CE9  33P_0402_50V8J  [C_0402]  230.6 75.93 270 top
CE10  1U_0402_6.3V6K  [C_0402]  245.08 79.36 270 top
CE11  0.1U_0201_10V6K  [C_0201]  252.53 74.61 90 top
CE12  1U_0402_6.3V6K  [C_0402]  243.3 78.44 90 top
CE13  0.1U_0201_10V6K  [C_0201]  252.96 59.29 270 top
CE14  1U_0402_6.3V6K  [C_0402]  253.85 59.29 270 top
CE15  1U_0402_6.3V6K  [C_0402]  255.75 75.01 90 top
CE16  0.1U_0201_10V6K  [C_0201]  246.3 65.95 180 top
CE17  0.1U_0201_10V6K  [C_0201]  246.56 71.79 180 top
CE18  0.1U_0201_10V6K  [C_0201]  260.58 59.29 270 top
CE19  0.1U_0201_10V6K  [C_0201]  258.8 75.01 90 top
CE20  0.1U_0201_10V6K  [C_0201]  254.73 74.63 90 top
CE21  10U_0603_10V6M  [C_0603]  264.74 56.99 270 top
CE22  0.1U_0201_10V6K  [C_0201]  256.51 59.42 270 top
CE23  0.1U_0201_10V6K  [C_0201]  262.53 67.73 0 top
CE24  2200P_0402_50V7K  [C_0402]  246.23 62.82 90 top
CE25  0.1U_0201_10V6K  [C_0201]  259.69 75.01 90 top
CE26  2200P_0402_50V7K  [C_0402]  246.23 60.92 90 top
CE27  2200P_0402_50V7K  [C_0402]  248.05 60.23 0 top
CE28  33P_0402_50V8J  [C_0402]  248.43 76.87 0 top
CE29  33P_0402_50V8J  [C_0402]  247.44 76.87 180 top
CE30  1U_0402_6.3V6K  [C_0402]  259.69 77.81 90 top
CE31  4.7U_0603_6.3V6K  [C_0603]  246.29 64.8 180 top
CE32  10U_0603_10V6M  [C_0603]  80.24 91.92 270 top
CE34  4.7P_0402_50V8C  [C_0402]  256.64 57.01 270 top
CE35  100P_0402_50V8J  [C_0402]  142.4 90.41 270 top
CE36  0.1U_0402_25V6  [C_0402]  258.3 59.29 0 top
CE37  100P_0402_50V8J  [C_0402]  225.14 53.3 90 top
CE38  0.1U_0402_25V6  [C_0402]  250.87 59.44 270 top
CE39  100P_0402_50V8J  [C_0402]  110.13 105.83 0 top
CE40  4700P_0402_25V7K  [C_0402]  246.3 66.84 180 top
CE44  1U_0402_6.3V6K  [C_0402]  243.25 76.81 180 top
CE45  1U_0402_6.3V6K  [C_0402]  245.1 75.92 90 top
CE46  100P_0402_50V8J  [C_0402]  270.3 66.58 180 bottom
CE47  4700P_0402_25V7K  [C_0402]  243.25 60.18 270 top
CE52  0.1U_0402_25V6  [C_0402]  251.44 54.92 180 top
CI1  100U_1206_6.3V6M  [C_1206]  57.7 131.22 90 bottom
CI3  0.1U_0201_10V6K  [C_0201]  72.18 125.71 270 top
CI4  0.1U_0402_25V6  [C_0402]  67.22 121.9 270 top
CI5  0.1U_0402_25V6  [C_0402]  66.33 121.9 270 top
CI6  10U_0603_10V6M  [C_0603]  79.54 125 0 top
CI7  0.1U_0201_10V6K  [C_0201]  79.88 126.15 0 top
CI8  100U_1206_6.3V6M  [C_1206]  79.74 127.88 90 bottom
CI10  0.1U_0201_10V6K  [C_0201]  93.55 125.97 270 top
CI11  10U_0603_10V6M  [C_0603]  100.49 124.62 0 top
CI12  0.1U_0201_10V6K  [C_0201]  100.78 125.74 0 top
CI13  0.1U_0402_25V6  [C_0402]  282.62 95.99 270 bottom
CI14  100U_1206_6.3V6M  [C_1206]  286.23 95.35 270 bottom
CI16  0.1U_0402_25V6  [C_0402]  283.51 95.99 270 bottom
CI17  0.1U_0201_10V6K  [C_0201]  284.33 93.79 270 bottom
CI19  0.1U_0201_10V6K  [C_0201]  273.62 103.32 180 top
CI27  0.1U_0402_25V6  [C_0402]  91.54 121.52 270 top
CI28  0.1U_0402_25V6  [C_0402]  92.43 121.52 270 top
CI29  0.1U_0402_25V6  [C_0402]  276.32 96.94 180 top
CI30  0.1U_0402_25V6  [C_0402]  276.32 97.82 180 top
CI31  10U_0402_6.3V6M  [C_0402]  273.78 104.17 180 top
CI32  150U_B2_6.3VM_R35M  [C_B2-NPM]  286.23 95.39 90 bottom
CI33  47U_0603_6.3V6M  [C_0603]  273.5 105.33 180 top
CI34  47U_0603_6.3V6M  [C_0603]  273.5 106.57 180 top
CL1  0.1U_0402_25V6  [C_0402]  257.02 88.76 270 top
CL2  0.1U_0402_25V6  [C_0402]  257.91 88.76 270 top
CL3  0.1U_0201_10V6K  [C_0201]  268.01 94.46 270 top
CL4  10U_0603_10V6M  [C_0603]  269.09 94.59 270 top
CL5  0.1U_0402_25V6  [C_0402]  259.69 87.84 90 top
CL6  0.1U_0402_25V6  [C_0402]  260.58 87.84 90 top
CL7  0.1U_0201_10V6K  [C_0201]  265.78 91.69 0 top
CL8  0.1U_0201_10V6K  [C_0201]  262.4 88.55 270 top
CL9  0.1U_0201_10V6K  [C_0201]  258.8 88.76 270 top
CL10  0.1U_0201_10V6K  [C_0201]  256.13 88.76 270 top
CL11  0.1U_0201_10V6K  [C_0201]  261.47 98.83 90 top
CL12  22U_0603_6.3V6M  [C_0603]  263.4 88.78 270 top
CL13  27P_0402_50V8J  [C_0402]  268.91 95.86 180 top
CL14  27P_0402_50V8J  [C_0402]  265.02 99.42 270 top
CL15  0.1U_0201_10V6K  [C_0201]  251.69 95.33 90 top
CL16  0.1U_0201_10V6K  [C_0201]  278.48 114.4 270 top
CL17  0.1U_0201_10V6K  [C_0201]  277.21 114.4 270 top
CL18  470P_0402_50V7K  [C_0402]  285.98 121.78 270 top
CL19  0.1U_0201_10V6K  [C_0201]  266.55 122.41 270 top
CL20  0.1U_0201_10V6K  [C_0201]  270.86 114.4 270 top
CL21  0.1U_0201_10V6K  [C_0201]  269.59 114.4 270 top
CL22  150P_1808_2.5KV8J  [C_1808]  290.18 128.81 180 bottom
CL25  0.1U_0201_10V6K  [C_0201]  255.5 109.56 90 top
CL26  0.1U_0201_10V6K  [C_0201]  255.5 106.38 90 top
CL27  0.1U_0201_10V6K  [C_0201]  267.43 109.56 90 top
CL28  22U_0805_6.3V6M  [C_0805]  254.7 93.89 180 top
CMOS1  SHORT PADS~D  [SHORTPADS-NPM]  204.95 78.65 90 bottom
CN19  0.1U_0201_10V6K  [C_0201]  30.57 57.82 0 top
CN20  0.01UF_0402_25V7K  [C_0402]  23.1 51.98 180 top
CN21  0.22U_0402_10V6K  [C_0402]  28.42 59.55 270 top
CN22  0.22U_0402_10V6K  [C_0402]  27.53 59.55 270 top
CN23  0.22U_0402_10V6K  [C_0402]  25.75 59.55 270 top
CN24  0.22U_0402_10V6K  [C_0402]  26.64 59.55 270 top
CN25  0.22U_0402_10V6K  [C_0402]  28.36 49.96 90 top
CN26  0.22U_0402_10V6K  [C_0402]  27.47 49.96 90 top
CN29  0.1U_0201_10V6K  [C_0201]  44.54 57.44 0 top
CN30  0.01UF_0402_25V7K  [C_0402]  37.01 51.6 180 top
CN31  0.22U_0402_10V6K  [C_0402]  41.63 59.04 270 top
CN32  0.22U_0402_10V6K  [C_0402]  42.52 59.04 270 top
CN33  0.22U_0402_10V6K  [C_0402]  39.85 59.04 270 top
CN34  0.22U_0402_10V6K  [C_0402]  40.74 59.04 270 top
CN35  0.22U_0402_10V6K  [C_0402]  42.52 50.12 90 top
CN36  0.22U_0402_10V6K  [C_0402]  41.63 50.12 90 top
CN41  0.1U_0201_10V6K  [C_0201]  22.02 37.88 180 top
CN42  0.1U_0201_10V6K  [C_0201]  10.93 36.28 90 top
CR8  0.1U_0201_10V6K  [C_0201]  269.34 84.82 0 top
CR9  4.7U_0603_6.3V6K  [C_0603]  270.04 76.36 270 top
CR10  0.1U_0201_10V6K  [C_0201]  269.05 76.25 270 top
CR13  0.1U_0201_10V6K  [C_0201]  265.78 77.2 270 top
CR23  5P_0402_50V8C  [C_0402]  273.16 77.5 180 top
CR24  0.1U_0402_25V6  [C_0402]  263.67 81.7 0 top
CR25  0.1U_0402_25V6  [C_0402]  263.67 80.81 0 top
CR26  0.1U_0402_25V6  [C_0402]  263.67 79.92 0 top
CR27  0.1U_0402_25V6  [C_0402]  263.67 79.03 0 top
CR35  1U_0402_6.3V6K  [C_0402]  270.86 84.16 90 top
CR36  0.1U_0201_10V6K  [C_0201]  267.57 76.49 180 top
CR37  1U_0402_6.3V6K  [C_0402]  270.69 79.28 180 bottom
CR38  4.7U_0603_6.3V6K  [C_0603]  269.97 72.61 270 bottom
CR39  0.1U_0201_10V6K  [C_0201]  271.12 72.25 270 bottom
CR40  4.7U_0603_6.3V6K  [C_0603]  302.8 56.04 180 top
CR41  0.1U_0201_10V6K  [C_0201]  302.56 57.18 180 top
CR42  10U_0402_6.3V6M  [C_0402]  269.11 85.59 0 top
CR43  10U_0402_6.3V6M  [C_0402]  267.57 75.6 180 top
CV1  0.1U_0402_25V6  [C_0402]  93.07 105.55 145 top
CV2  0.1U_0402_25V6  [C_0402]  92.53 104.81 145 top
CV3  0.1U_0402_25V6  [C_0402]  91.98 104.08 145 top
CV4  0.1U_0402_25V6  [C_0402]  91.44 103.34 145 top
CV5  0.1U_0402_25V6  [C_0402]  90.9 102.6 145 top
CV6  0.1U_0402_25V6  [C_0402]  90.36 101.86 145 top
CV7  0.1U_0603_50V7K  [C_0603]  92.56 112.37 90 top
CV8  0.1U_0201_10V6K  [C_0201]  91.93 109.36 90 top
CV9  10U_0603_10V6M  [C_0603]  90.84 108.68 90 top
CV10  0.01UF_0402_25V7K  [C_0402]  88.17 106.19 90 top
CV11  1000P_0402_50V7K  [C_0402]  86.84 112.48 90 top
CV12  0.1U_0603_50V7K  [C_0603]  93.83 112.37 90 top
CV13  0.1U_0402_25V6  [C_0402]  236.19 126.22 270 bottom
CV14  0.1U_0402_25V6  [C_0402]  237.08 126.22 270 bottom
CV17  0.1U_0402_25V6  [C_0402]  232.64 126.22 270 bottom
CV18  0.1U_0402_25V6  [C_0402]  233.53 126.22 270 bottom
CV21  0.1U_0402_25V6  [C_0402]  234.41 126.22 270 bottom
CV22  0.1U_0402_25V6  [C_0402]  235.3 126.22 270 bottom
CV23  0.1U_0201_10V6K  [C_0201]  246.61 128 90 bottom
CV26  0.1U_0201_10V6K  [C_0201]  240.41 128.9 270 bottom
CV27  10U_0603_10V6M  [C_0603]  241.65 129 270 bottom
CV28  0.1U_0402_25V6  [C_0402]  230.86 126.22 270 bottom
CV29  0.1U_0402_25V6  [C_0402]  231.75 126.22 270 bottom
CV60  2.2U_0402_6.3V6M  [C_0402]  253.01 125.89 0 top
CV61  0.01UF_0402_25V7K  [C_0402]  245.33 126.6 180 top
CV62  0.01UF_0402_25V7K  [C_0402]  245.16 112.43 180 top
CV66  0.1U_0201_10V6K  [C_0201]  253.05 115.86 0 top
CV69  0.1U_0201_10V6K  [C_0201]  245.06 125.81 180 top
CV70  0.1U_0201_10V6K  [C_0201]  251.53 126.23 90 top
CV71  0.1U_0402_25V6  [C_0402]  253.96 116.82 180 top
CV72  0.1U_0402_25V6  [C_0402]  253.96 117.71 180 top
CV73  0.1U_0402_25V6  [C_0402]  253.96 118.6 180 top
CV74  0.1U_0402_25V6  [C_0402]  253.96 119.49 180 top
CV75  0.1U_0402_25V6  [C_0402]  253.96 120.38 180 top
CV76  0.1U_0402_25V6  [C_0402]  253.96 121.27 180 top
CV77  0.1U_0402_25V6  [C_0402]  253.96 122.16 180 top
CV78  0.1U_0402_25V6  [C_0402]  253.96 123.05 180 top
CV79  0.1U_0402_25V6  [C_0402]  250.65 127.06 270 top
CV80  0.1U_0402_25V6  [C_0402]  249.76 127.06 270 top
CV82  10U_0603_10V6M  [C_0603]  217.4 109.14 270 bottom
CV83  0.1U_0201_10V6K  [C_0201]  216.95 117.25 90 bottom
CV84  0.1U_0201_10V6K  [C_0201]  216.94 119.99 90 bottom
CV85  0.01UF_0402_25V7K  [C_0402]  216.01 111.86 180 bottom
CV86  0.01UF_0402_25V7K  [C_0402]  213.51 117.86 270 bottom
CV87  1U_0603_10V6K  [C_0603]  216.19 109.14 270 bottom
CV88  0.1U_0201_10V6K  [C_0201]  215.77 112.62 180 bottom
CV89  0.01UF_0402_25V7K  [C_0402]  212.62 117.86 270 bottom
CV90  10U_0603_10V6M  [C_0603]  218.77 111.48 0 bottom
CV91  0.1U_0201_10V6K  [C_0201]  218.97 112.62 0 bottom
CV92  0.01UF_0402_25V7K  [C_0402]  215.62 120.17 90 bottom
CV93  0.01UF_0402_25V7K  [C_0402]  213.53 116.11 270 bottom
CV94  10U_0603_10V6M  [C_0603]  222.22 120.75 270 bottom
CV95  0.1U_0201_10V6K  [C_0201]  219.5 120.76 180 bottom
CV96  0.01UF_0402_25V7K  [C_0402]  213.47 119.6 180 bottom
CV97  0.01UF_0402_25V7K  [C_0402]  213.6 114.35 180 bottom
CV98  0.01UF_0402_25V7K  [C_0402]  213.46 118.74 180 bottom
CV99  0.01UF_0402_25V7K  [C_0402]  219.89 116.75 180 bottom
CV100  0.1U_0201_10V6K  [C_0201]  217.83 120 90 bottom
CV101  10U_0603_10V6M  [C_0603]  221.08 116.81 270 bottom
CV102  0.1U_0402_25V6  [C_0402]  219.05 109.18 90 top
CV103  0.1U_0402_25V6  [C_0402]  218.16 109.18 90 top
CV104  0.1U_0402_25V6  [C_0402]  217.78 106.76 90 top
CV105  0.1U_0402_25V6  [C_0402]  216.89 106.76 90 top
CV106  0.1U_0402_25V6  [C_0402]  216.51 109.18 90 top
CV107  0.1U_0402_25V6  [C_0402]  215.62 109.18 90 top
CV108  0.1U_0402_25V6  [C_0402]  214.73 108.16 90 top
CV109  0.1U_0402_25V6  [C_0402]  213.84 108.16 90 top
CV110  0.1U_0402_25V6  [C_0402]  220.44 106.76 90 top
CV111  0.1U_0402_25V6  [C_0402]  219.56 106.76 90 top
CV113  18P_0402_50V8J  [C_0402]  223.61 109.32 0 top
CV114  0.1U_0201_10V6K  [C_0201]  202.13 105.66 180 bottom
CV115  18P_0402_50V8J  [C_0402]  222.74 109.32 180 top
CV118  0.1U_0201_10V6K  [C_0201]  206.14 121.07 0 bottom
CV119  0.1U_0402_25V6  [C_0402]  196.52 121.7 180 bottom
CV120  0.1U_0402_25V6  [C_0402]  196.52 123.73 180 bottom
CV121  0.1U_0201_10V6K  [C_0201]  206.09 115.36 0 bottom
CV122  0.1U_0402_25V6  [C_0402]  196.52 116.11 180 bottom
CV123  0.1U_0402_25V6  [C_0402]  196.52 118.02 180 bottom
CV145  0.1U_0402_25V6  [C_0402]  247.75 41.82 90 bottom
CV146  0.1U_0402_25V6  [C_0402]  248.64 41.82 90 bottom
CV147  0.1U_0402_25V6  [C_0402]  250.42 41.82 90 bottom
CV148  0.1U_0402_25V6  [C_0402]  249.53 41.82 90 bottom
CV149  0.1U_0402_25V6  [C_0402]  248.77 52.94 270 top
CV150  0.1U_0402_25V6  [C_0402]  247.88 52.94 270 top
CV152  0.1U_0402_25V6  [C_0402]  249.65 52.94 270 top
CV153  0.1U_0402_25V6  [C_0402]  250.54 52.94 270 top
CV156  0.1U_0402_25V6  [C_0402]  251.43 52.94 270 top
CV157  0.1U_0402_25V6  [C_0402]  252.32 52.94 270 top
CV374  0.01U_0402_50V7K  [C_0402]  87.73 114.26 90 top
CV501  0.1U_0402_25V6  [C_0402]  226.08 128.05 0 top
CV502  0.1U_0402_25V6  [C_0402]  226.08 128.94 0 top
CV503  0.1U_0402_25V6  [C_0402]  223.92 126.78 0 top
CV504  0.1U_0402_25V6  [C_0402]  223.92 127.67 0 top
CV505  0.1U_0402_25V6  [C_0402]  226.08 125.51 0 top
CV506  0.1U_0402_25V6  [C_0402]  226.08 126.4 0 top
CV507  0.1U_0402_25V6  [C_0402]  223.92 124.24 0 top
CV508  0.1U_0402_25V6  [C_0402]  223.92 125.13 0 top
CV509  0.01UF_0402_25V7K  [C_0402]  217.65 126.22 270 bottom
CV510  0.1U_0201_10V6K  [C_0201]  245.16 113.32 180 top
CV600  0.1U_0201_10V6K  [C_0201]  240.31 106.71 0 top
CV601  0.1U_0201_10V6K  [C_0201]  227 111.54 180 top
CV602  0.1U_0201_10V6K  [C_0201]  227 106.97 180 top
CV603  0.01UF_0402_25V7K  [C_0402]  238.99 115.43 270 top
CV604  0.01UF_0402_25V7K  [C_0402]  240.31 111.67 0 top
CV605  2.2U_0402_6.3V6M  [C_0402]  229.21 114.51 90 top
CV606  0.1U_0402_25V6  [C_0402]  236.32 115.43 270 top
CV607  0.1U_0402_25V6  [C_0402]  235.43 115.43 270 top
CV608  0.1U_0402_25V6  [C_0402]  234.54 115.43 270 top
CV609  0.1U_0402_25V6  [C_0402]  233.65 115.43 270 top
CV610  0.1U_0402_25V6  [C_0402]  232.76 115.43 270 top
CV611  0.1U_0402_25V6  [C_0402]  231.87 115.43 270 top
CV612  0.1U_0402_25V6  [C_0402]  230.99 115.43 270 top
CV613  0.1U_0402_25V6  [C_0402]  230.1 115.43 270 top
CV615  0.1U_0201_10V6K  [C_0201]  226.1 116.06 0 bottom
CV616  1U_0402_6.3V6K  [C_0402]  224.83 121.24 90 bottom
CV617  10U_0603_10V6M  [C_0603]  223.33 102.64 90 bottom
CV618  10U_0603_10V6M  [C_0603]  214.91 104.03 270 bottom
CV619  1U_0402_6.3V6K  [C_0402]  215.33 105.81 180 bottom
CZ1  0.1U_0201_10V6K  [C_0201]  98.28 113.49 145 top
CZ2  0.1U_0201_10V6K  [C_0201]  101.04 117.48 235 top
CZ10  0.1U_0201_10V6K  [C_0201]  292.9 10.68 90 bottom
CZ11  0.1U_0201_10V6K  [C_0201]  292.31 10.73 90 bottom
CZ12  0.1U_0201_10V6K  [C_0201]  288.52 11.41 270 bottom
CZ13  0.1U_0402_25V6  [C_0402]  253.44 52.92 270 top
CZ14  0.1U_0402_25V6  [C_0402]  254.33 52.92 270 top
CZ15  0.1U_0201_10V6K  [C_0201]  244.7 53.04 90 top
CZ16  .047U_0402_16V7K  [C_0402]  262.1 52.03 90 top
CZ17  0.1U_0201_10V6K  [C_0201]  243.81 53.04 90 top
CZ18  0.1U_0201_10V6K  [C_0201]  261.21 52.03 90 top
CZ19  4.7U_0603_6.3V6K  [C_0603]  242.67 53.06 90 top
CZ20  .047U_0402_16V7K  [C_0402]  262.99 52.03 90 top
CZ21  0.1U_0402_25V6  [C_0402]  260.7 55.25 270 top
CZ22  0.1U_0402_25V6  [C_0402]  261.59 55.25 270 top
CZ23  470P_0402_50V7K  [C_0402]  283.13 111.03 180 top
CZ24  0.1U_0201_10V6K  [C_0201]  286.95 11.48 180 bottom
CZ27  0.1U_0201_10V6K  [C_0201]  282.05 10.36 0 bottom
CZ28  0.1U_0201_10V6K  [C_0201]  279.63 6.21 90 top
CZ29  0.1U_0201_10V6K  [C_0201]  280.64 6.21 90 top
CZ30  330P_0402_50V8J  [C_0402]  284.07 11.27 0 top
CZ31  330P_0402_50V8J  [C_0402]  284.07 12.18 0 top
CZ34  0.1U_0201_10V6K  [C_0201]  269.09 70.98 270 top
CZ36  0.1U_0201_10V6K  [C_0201]  244.9 48.8 180 top
CZ37  470P_0402_50V7K  [C_0402]  244.9 47.91 180 top
CZ38  470P_0402_50V7K  [C_0402]  283.13 110.02 180 top
CZ39  0.1U_0201_10V6K  [C_0201]  284.99 103.74 270 top
CZ40  0.1U_0201_10V6K  [C_0201]  194.04 83.98 90 top
CZ41  470P_0402_50V7K  [C_0402]  195.02 84.02 90 top
CZ42  470P_0402_50V7K  [C_0402]  198.96 82.74 0 top
CZ43  0.1U_0201_10V6K  [C_0201]  197.53 82.7 180 top
CZ44  0.1U_0201_10V6K  [C_0201]  82.85 119.92 180 bottom
CZ45  470P_0402_50V7K  [C_0402]  82.85 118.78 180 bottom
CZ46  1000P_0402_50V7K  [C_0402]  244.9 47.02 180 top
CZ47  0.1U_0201_10V6K  [C_0201]  244.69 46.11 180 top
CZ48  0.1U_0201_10V6K  [C_0201]  285.39 15.66 0 top
CZ50  0.1U_0201_10V6K  [C_0201]  285 112.8 0 top
CZ51  .047U_0402_16V7K  [C_0402]  283.67 109.24 0 bottom
CZ52  .047U_0402_16V7K  [C_0402]  272.25 89.75 0 top
CZ53  33P_0402_50V8J  [C_0402]  283.67 108.35 0 bottom
CZ54  22U_0603_6.3V6M  [C_0603]  272.01 87.71 0 top
CZ55  33P_0402_50V8J  [C_0402]  272.25 88.86 0 top
CZ57  150U_B2_6.3VM_R35M  [C_B2]  283.68 106.08 180 bottom
CZ58  0.1U_0402_25V6  [C_0402]  283.99 100.88 180 bottom
CZ59  0.1U_0402_25V6  [C_0402]  283.99 101.77 180 bottom
CZ60  22U_0603_6.3V6M  [C_0603]  22.26 36.74 180 top
CZ61  22U_0603_6.3V6M  [C_0603]  11.91 36.17 90 top
CZ64  0.1U_0201_10V6K  [C_0201]  82.75 116.28 180 bottom
CZ65  33P_0402_50V8J  [C_0402]  284.53 117.89 180 bottom
CZ66  33P_0402_50V8J  [C_0402]  284.53 116.87 180 bottom
CZ67  33P_0402_50V8J  [C_0402]  284.53 119.41 180 bottom
CZ68  .047U_0402_16V7K  [C_0402]  295.4 11.63 0 bottom
CZ69  470P_0402_50V7K  [C_0402]  82.85 117.89 180 bottom
CZ71  0.1U_0201_10V6K  [C_0201]  220.15 68.36 0 top
CZ72  10U_0603_10V6M  [C_0603]  219.66 67.43 0 top
CZ73  0.1U_0201_10V6K  [C_0201]  220.69 72.12 270 top
CZ74  0.1U_0201_10V6K  [C_0201]  214.86 74.54 180 top
CZ75  0.1U_0201_10V6K  [C_0201]  210.49 68.74 180 top
CZ76  10U_0603_10V6M  [C_0603]  215.86 75.51 180 top
CZ77  0.1U_0402_25V6  [C_0402]  211.4 75.42 270 top
CZ78  0.1U_0201_10V6K  [C_0201]  117.32 130.26 90 top
CZ82  0.1U_0201_10V6K  [C_0201]  157.69 115.5 180 bottom
CZ84  1U_0402_6.3V6K  [C_0402]  167.61 119.66 90 bottom
CZ85  0.1U_0201_10V6K  [C_0201]  172.66 115.09 90 bottom
CZ87  1U_0402_6.3V6K  [C_0402]  164.82 119.59 90 bottom
CZ89  0.1U_0201_10V6K  [C_0201]  279.3 70.14 0 top
CZ90  220P_0402_50V7K  [C_0402]  279.17 69.25 0 top
CZ91  1000P_0402_50V7K  [C_0402]  279.17 68.36 0 top
CZ92  0.1U_0201_10V6K  [C_0201]  279.17 67.47 0 top
CZ94  0.1U_0201_10V6K  [C_0201]  293.65 9.18 0 top
CZ95  1U_0402_6.3V6K  [C_0402]  113.78 126.46 180 top
CZ113  1U_0402_6.3V6K  [C_0402]  114.49 71.17 90 top
CZ114  0.1U_0201_10V6K  [C_0201]  109.22 72.36 90 top
CZ115  0.1U_0402_10V7K  [C_0402]  87.11 117.17 180 top
D19  -  [RB751S40T1G_SOD523-2]  177.33 123.29 270 bottom
D20  -  [L30ESD24VC3-2_SOT23-3]  136.65 129.7 90 top
DA1  AZ5123-02S.R7G_SOT23-3  [L03ESDL5V0CC3-2_SOT23-3]  286.2 45.63 270 top
DA2  -  [L03ESDL5V0CC3-2_SOT23-3]  286.19 41.75 270 top
DA3  AZ5123-02S.R7G_SOT23-3  [L03ESDL5V0CC3-2_SOT23-3]  286.2 51.91 270 top
DA4  -  [RB751S40T1G_SOD523-2]  296.92 69.67 180 top
DA5  -  [RB751S40T1G_SOD523-2]  296.92 68.53 180 top
DA6  -  [L03ESDL5V0CC3-2_SOT23-3]  282.95 36.48 90 top
DA7  -  [L03ESDL5V0CC3-2_SOT23-3]  282.95 28.99 90 top
DE1  -  [RB751S40T1G_SOD523-2]  79.03 91.79 270 top
DI1  -  [L05ESDL5V0NA-4_SLP2510P8-10-9]  65.01 125.2 180 top
DI2  -  [AZC199-02SPR7G_SOT23-3]  69.7 125.41 180 top
DI3  -  [AZC199-02SPR7G_SOT23-3]  87.94 124.72 90 top
DI4  -  [L05ESDL5V0NA-4_SLP2510P8-10-9]  287.18 99.59 90 bottom
DI5  -  [AZC199-02SPR7G_SOT23-3]  287 95.87 0 top
DI6  -  [L05ESDL5V0NA-4_SLP2510P8-10-9]  90.16 125.2 180 top
DI7  -  [L05ESDL5V0NA-4_SLP2510P8-10-9]  280.68 95.55 270 top
DV1  -  [BAT54CW_SOT323-3]  98.42 109.76 325 top
DV2  -  [BAT54CW_SOT323-3]  93.58 108.39 55 top
DV3  -  [BAT54CW_SOT323-3]  83.03 109.11 0 top
DV4  -  [AZC199-02SPR7G_SOT23-3]  108.4 117.64 90 bottom
DZ1  -  [RB751S40T1G_SOD523-2]  257.53 48.23 90 top
DZ2  -  [RB751S40T1G_SOD523-2]  258.67 48.23 90 top
DZ3  -  [RB751S40T1G_SOD523-2]  278.99 16.86 90 top
DZ4  -  [RB751S40T1G_SOD523-2]  278.99 20.38 270 top
DZ5  -  [RB751S40T1G_SOD523-2]  272 91.65 0 top
DZ6  -  [RB751S40T1G_SOD523-2]  273.43 93.77 180 top
DZ7  -  [RB751S40T1G_SOD523-2]  296.72 8.44 180 top
FD1  FIDUCIAL MARK~D  [FIDUCIAL_C40M80]  56.16 132.51 0 top
FD2  FIDUCIAL MARK~D  [FIDUCIAL_C40M80]  62.79 122.82 180 bottom
FD3  FIDUCIAL MARK~D  [FIDUCIAL_C40M80]  297.16 28.86 0 top
FD4  FIDUCIAL MARK~D  [FIDUCIAL_C40M80]  297.41 16.42 180 bottom
H1  H3P4  [H_3P4]  123.79 104.27 0 top
H2  H3P4  [H_3P4]  123.79 82.13 0 top
H3  H3P4  [H_3P4]  183.61 104.27 0 top
H4  H3P4  [H_3P4]  183.61 82.13 0 top
H5  -  [H_1P1N]  135.1 105.36 0 top
H6  -  [H_1P1N]  176.22 82.25 0 top
